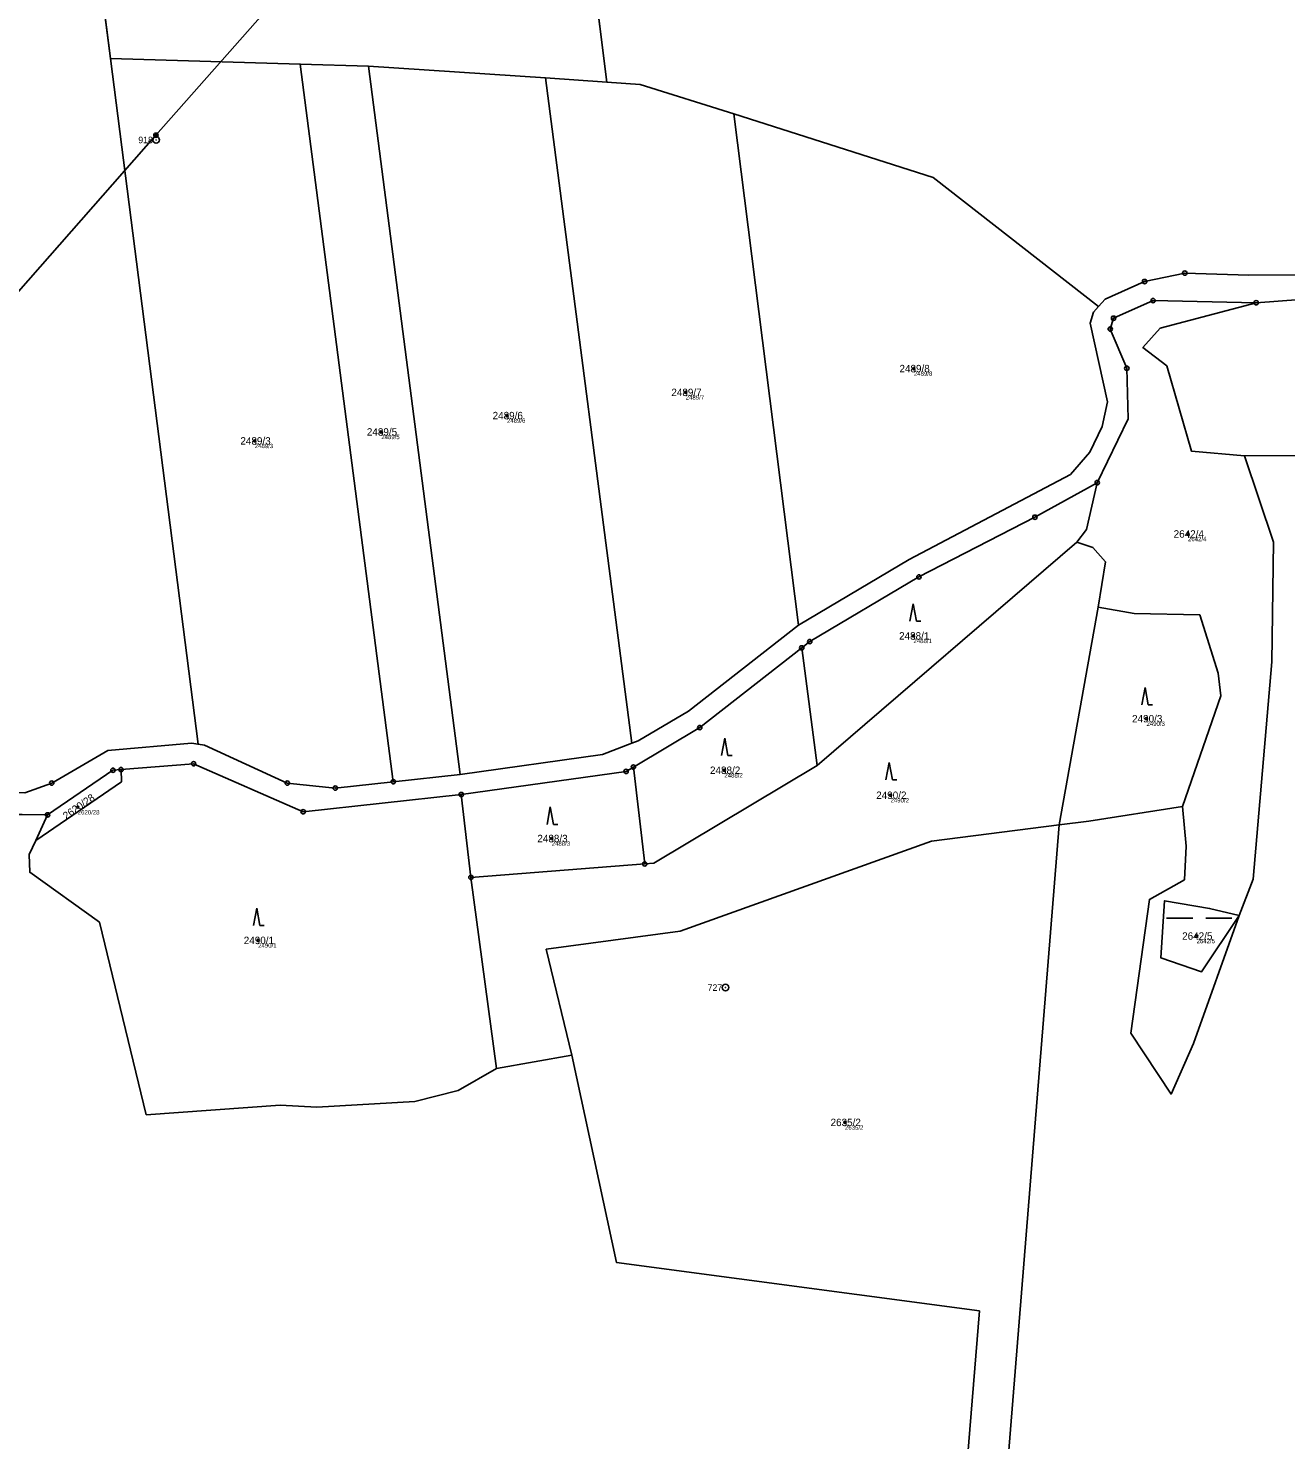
# Model space of a CAD drawing. Extents: x -761891 to -756141, y -1178507 to -1171885.
# Drawn here: x -759249.4 to -758960.9, y -1175617.5 to -1175293.7 of the extents above; entities that cross this region are included whole.
import ezdxf

# ---------------------------------------------------------------- set-up
doc = ezdxf.new("R2010")
doc.units = 0
for name, color, linetype in [('Definiční body', 7, 'Continuous'), ('Hranice parcel', 7, 'Continuous'), ('Parcelní čísla', 7, 'Continuous'), ('Polygon parcely', 7, 'Continuous'), ('Poz předměty', 7, 'Continuous'), ('Značky bodu BP', 7, 'Continuous'), ('Značky kultur', 7, 'Continuous')]:
    doc.layers.add(name, color=color, linetype=linetype)

msp = doc.modelspace()

# ---------------------------------------------------------------- linework, layer by layer
at = {"layer": 'Definiční body'}
for centre in [(-759046.21, -1175371.74), (-759098.55, -1175377.2), (-759139.55, -1175382.52), (-759197.41, -1175388.33), (-759168.39, -1175386.27), (-758983.32, -1175409.67), (-759046.31, -1175433.06), (-758992.85, -1175452.05), (-759089.68, -1175463.88), (-759238.01, -1175472.36), (-759051.56, -1175469.61), (-759129.29, -1175479.54), (-758981.36, -1175501.9), (-759196.63, -1175502.91), (-759062.01, -1175544.66)]:
    msp.add_circle(centre, 0.25, dxfattribs=at)
at = {"layer": 'Hranice parcel'}
for p, q in [((-759230.51, -1175300.62), (-759239.1, -1175233.43)), ((-759124.57, -1175242.76), (-759116.61, -1175306.03)), ((-759210.41, -1175457.91), (-759230.51, -1175300.62)), ((-759186.97, -1175301.88), (-759230.51, -1175300.62)), ((-759165.64, -1175466.52), (-759186.97, -1175301.88)), ((-759186.97, -1175301.88), (-759171.32, -1175302.34)), ((-759171.32, -1175302.34), (-759150.26, -1175464.85)), ((-759171.32, -1175302.34), (-759130.69, -1175305.08)), ((-759130.69, -1175305.08), (-759110.92, -1175457.7)), ((-759130.69, -1175305.08), (-759116.61, -1175306.03)), ((-759087.54, -1175313.33), (-759072.7, -1175430.56)), ((-759008.83, -1175411.55), (-759068.36, -1175462.82)), ((-759003.9, -1175426.45), (-759012.92, -1175476.42)), ((-759071.93, -1175435.8), (-759068.36, -1175462.82)), ((-759150.26, -1175464.85), (-759165.64, -1175466.52)), ((-759110.54, -1175463.15), (-759107.94, -1175485.36)), ((-759147.83, -1175488.47), (-759150.05, -1175469.45)), ((-759274.94, -1175473.79), (-759244.94, -1175474.11)), ((-759247.64, -1175479.98), (-759244.94, -1175474.11)), ((-759107.94, -1175485.36), (-759147.83, -1175488.47)), ((-759141.95, -1175532.33), (-759147.83, -1175488.47)), ((-759124.69, -1175529.2), (-759141.95, -1175532.33))]:
    msp.add_line(p, q, dxfattribs=at)
for points in [[(-758695.3, -1175253.59), (-758701.44, -1175256.15), (-758706.31, -1175261.2), (-758730.9, -1175293.88), (-758746.46, -1175305.02), (-758759.1, -1175309.68), (-758817.04, -1175324.96), (-758849.31, -1175338.47), (-758893.74, -1175347.18), (-758929.46, -1175350.12), (-758969.35, -1175350.34), (-758984.06, -1175349.84), (-758993.3, -1175351.77), (-759002.36, -1175355.79), (-759003.87, -1175357.51)], [(-759116.61, -1175306.03), (-759108.97, -1175306.54), (-759087.54, -1175313.33)], [(-759087.54, -1175313.33), (-759041.78, -1175327.91), (-759003.87, -1175357.51)], [(-758967.69, -1175356.63), (-758957.61, -1175355.92), (-758936.92, -1175355.2), (-758892.8, -1175353.02)], [(-759003.87, -1175357.51), (-759005.01, -1175358.82), (-759005.75, -1175361.32), (-759001.76, -1175379.4), (-759003.02, -1175385), (-759005.87, -1175390.89), (-759010.3, -1175396.05), (-759047.29, -1175415.5), (-759072.7, -1175430.56)], [(-759004.16, -1175397.91), (-758997.06, -1175383.23), (-758997.36, -1175371.67), (-759001.15, -1175362.68), (-759000.41, -1175360.18), (-758991.35, -1175356.15), (-758967.69, -1175356.63)], [(-758967.69, -1175356.63), (-758989.69, -1175362.44), (-758993.67, -1175366.93), (-758988.15, -1175371.11), (-758982.56, -1175390.67), (-758970.34, -1175391.79)], [(-758970.34, -1175391.79), (-758896.65, -1175391.68), (-758878, -1175385.58), (-758877.56, -1175382.43)], [(-758984.56, -1175472.16), (-758983.74, -1175481.33), (-758984.15, -1175488.98), (-758992.19, -1175493.5), (-758996.44, -1175524.19), (-758987.22, -1175538.18), (-758982.03, -1175526.53), (-758971.62, -1175497.23), (-758968.41, -1175488.86), (-758964.07, -1175438.99), (-758963.69, -1175411.57), (-758970.34, -1175391.79)], [(-759071.93, -1175435.8), (-759070.1, -1175434.37), (-759045.06, -1175419.53), (-759018.46, -1175405.83), (-759004.16, -1175397.91)], [(-759004.16, -1175397.91), (-759006.64, -1175408.62), (-759008.83, -1175411.55)], [(-759008.83, -1175411.55), (-759005.17, -1175412.8), (-759002.27, -1175416.06), (-759003.9, -1175426.45)], [(-759003.9, -1175426.45), (-758995.67, -1175427.92), (-758980.65, -1175428.25), (-758976.42, -1175441.59), (-758975.79, -1175446.77), (-758984.56, -1175472.16)], [(-759072.7, -1175430.56), (-759097.94, -1175450.29), (-759109.43, -1175457.14), (-759110.92, -1175457.7)], [(-759110.54, -1175463.15), (-759095.34, -1175454.1), (-759071.93, -1175435.8)], [(-759210.41, -1175457.91), (-759211.95, -1175457.67), (-759231.12, -1175459.35), (-759243.97, -1175466.82), (-759250.12, -1175469.05), (-759272.12, -1175468.82)], [(-759165.64, -1175466.52), (-759178.94, -1175467.96), (-759189.96, -1175466.83), (-759208.95, -1175458.12), (-759210.41, -1175457.91)], [(-759110.92, -1175457.7), (-759117.67, -1175460.27), (-759150.26, -1175464.85)], [(-759228.09, -1175463.72), (-759211.43, -1175462.39), (-759186.31, -1175473.39), (-759150.05, -1175469.45)], [(-759068.36, -1175462.82), (-759105.84, -1175485.19), (-759107.94, -1175485.36)], [(-759228.09, -1175463.72), (-759227.96, -1175466.53), (-759247.64, -1175479.98)], [(-759244.94, -1175474.11), (-759229.95, -1175463.87), (-759228.09, -1175463.72)], [(-759150.05, -1175469.45), (-759112.22, -1175464.15), (-759110.54, -1175463.15)], [(-758984.56, -1175472.16), (-759006.08, -1175475.55), (-759012.92, -1175476.42)], [(-759124.69, -1175529.2), (-759130.53, -1175504.94), (-759099.79, -1175500.8), (-759042.19, -1175480.16), (-759012.92, -1175476.42)], [(-759012.92, -1175476.42), (-759024.01, -1175615.13), (-759035.11, -1175753.97)], [(-759247.64, -1175479.98), (-759249.13, -1175483.21), (-759249.01, -1175487.28), (-759233.01, -1175498.74), (-759222.29, -1175542.91), (-759191.58, -1175540.71), (-759183.19, -1175541.19), (-759160.7, -1175539.89), (-759150.72, -1175537.34), (-759141.95, -1175532.33)], [(-758971.62, -1175497.23), (-758980.2, -1175510.1), (-758989.59, -1175506.87), (-758988.69, -1175493.8), (-758978.38, -1175495.59), (-758971.62, -1175497.23)], [(-759044.36, -1175750.29), (-759031.17, -1175587.92), (-759114.42, -1175576.8), (-759124.69, -1175529.2)]]:
    msp.add_lwpolyline(points, dxfattribs=at)
at = {"layer": 'Polygon parcely'}
for points in [[(-759171.32, -1175302.34), (-759130.69, -1175305.08), (-759116.61, -1175306.03), (-759124.57, -1175242.76), (-759208.65, -1175251.43), (-759212.91, -1175218.59), (-759239.1, -1175233.43), (-759230.51, -1175300.62), (-759186.97, -1175301.88)], [(-759210.41, -1175457.91), (-759230.51, -1175300.62), (-759239.1, -1175233.43), (-759263.85, -1175246.81), (-759298.74, -1175260.61), (-759285.43, -1175364.72), (-759272.12, -1175468.82), (-759250.12, -1175469.05), (-759243.97, -1175466.82), (-759231.12, -1175459.35), (-759211.95, -1175457.67)], [(-759230.51, -1175300.62), (-759210.41, -1175457.91), (-759208.95, -1175458.12), (-759189.96, -1175466.83), (-759178.94, -1175467.96), (-759165.64, -1175466.52), (-759186.97, -1175301.88)], [(-759165.64, -1175466.52), (-759150.26, -1175464.85), (-759171.32, -1175302.34), (-759186.97, -1175301.88)], [(-759150.26, -1175464.85), (-759117.67, -1175460.27), (-759110.92, -1175457.7), (-759130.69, -1175305.08), (-759171.32, -1175302.34)], [(-759130.69, -1175305.08), (-759110.92, -1175457.7), (-759109.43, -1175457.14), (-759097.94, -1175450.29), (-759072.7, -1175430.56), (-759087.54, -1175313.33), (-759108.97, -1175306.54), (-759116.61, -1175306.03)], [(-759072.7, -1175430.56), (-759047.29, -1175415.5), (-759010.3, -1175396.05), (-759005.87, -1175390.89), (-759003.02, -1175385), (-759001.76, -1175379.4), (-759005.75, -1175361.32), (-759005.01, -1175358.82), (-759003.87, -1175357.51), (-759041.78, -1175327.91), (-759087.54, -1175313.33)], [(-758970.34, -1175391.79), (-758896.65, -1175391.68), (-758878, -1175385.58), (-758877.56, -1175382.43), (-758879.52, -1175379.64), (-758881.42, -1175374.43), (-758882.21, -1175367.16), (-758882.49, -1175364.51), (-758882.67, -1175362.89), (-758886.6, -1175357.63), (-758892.8, -1175353.02), (-758936.92, -1175355.2), (-758957.61, -1175355.92), (-758967.69, -1175356.63), (-758989.69, -1175362.44), (-758993.67, -1175366.93), (-758988.15, -1175371.11), (-758982.56, -1175390.67)], [(-758971.62, -1175497.23), (-758968.41, -1175488.86), (-758964.07, -1175438.99), (-758963.69, -1175411.57), (-758970.34, -1175391.79), (-758982.56, -1175390.67), (-758988.15, -1175371.11), (-758993.67, -1175366.93), (-758989.69, -1175362.44), (-758967.69, -1175356.63), (-758991.35, -1175356.15), (-759000.41, -1175360.18), (-759001.15, -1175362.68), (-758997.36, -1175371.67), (-758997.06, -1175383.23), (-759004.16, -1175397.91), (-759006.64, -1175408.62), (-759008.83, -1175411.55), (-759005.17, -1175412.8), (-759002.27, -1175416.06), (-759003.9, -1175426.45), (-758995.67, -1175427.92), (-758980.65, -1175428.25), (-758976.42, -1175441.59), (-758975.79, -1175446.77), (-758984.56, -1175472.16), (-758983.74, -1175481.33), (-758984.15, -1175488.98), (-758992.19, -1175493.5), (-758996.44, -1175524.19), (-758987.22, -1175538.18), (-758982.03, -1175526.53)], [(-759068.36, -1175462.82), (-759008.83, -1175411.55), (-759006.64, -1175408.62), (-759004.16, -1175397.91), (-759018.46, -1175405.83), (-759045.06, -1175419.53), (-759070.1, -1175434.37), (-759071.93, -1175435.8)], [(-759012.92, -1175476.42), (-759003.9, -1175426.45), (-759002.27, -1175416.06), (-759005.17, -1175412.8), (-759008.83, -1175411.55), (-759068.36, -1175462.82), (-759105.84, -1175485.19), (-759107.94, -1175485.36), (-759147.83, -1175488.47), (-759141.95, -1175532.33), (-759124.69, -1175529.2), (-759130.53, -1175504.94), (-759099.79, -1175500.8), (-759042.19, -1175480.16)], [(-759003.9, -1175426.45), (-759012.92, -1175476.42), (-759006.08, -1175475.55), (-758984.56, -1175472.16), (-758975.79, -1175446.77), (-758976.42, -1175441.59), (-758980.65, -1175428.25), (-758995.67, -1175427.92)], [(-759110.54, -1175463.15), (-759107.94, -1175485.36), (-759105.84, -1175485.19), (-759068.36, -1175462.82), (-759071.93, -1175435.8), (-759095.34, -1175454.1)], [(-759228.09, -1175463.72), (-759227.96, -1175466.53), (-759247.64, -1175479.98), (-759249.13, -1175483.21), (-759249.01, -1175487.28), (-759233.01, -1175498.74), (-759222.29, -1175542.91), (-759191.58, -1175540.71), (-759183.19, -1175541.19), (-759160.7, -1175539.89), (-759150.72, -1175537.34), (-759141.95, -1175532.33), (-759147.83, -1175488.47), (-759150.05, -1175469.45), (-759186.31, -1175473.39), (-759211.43, -1175462.39)], [(-759228.09, -1175463.72), (-759229.95, -1175463.87), (-759244.94, -1175474.11), (-759247.64, -1175479.98), (-759227.96, -1175466.53)], [(-759110.54, -1175463.15), (-759112.22, -1175464.15), (-759150.05, -1175469.45), (-759147.83, -1175488.47), (-759107.94, -1175485.36)], [(-759124.69, -1175529.2), (-759114.42, -1175576.8), (-759031.17, -1175587.92), (-759044.36, -1175750.29), (-759041.58, -1175759.49), (-759035.11, -1175753.97), (-759024.01, -1175615.13), (-759012.92, -1175476.42), (-759042.19, -1175480.16), (-759099.79, -1175500.8), (-759130.53, -1175504.94)], [(-758971.62, -1175497.23), (-758980.2, -1175510.1), (-758989.59, -1175506.87), (-758988.69, -1175493.8), (-758978.38, -1175495.59)], [(-758971.62, -1175497.23), (-758978.38, -1175495.59), (-758988.69, -1175493.8), (-758989.59, -1175506.87), (-758980.2, -1175510.1)]]:
    msp.add_lwpolyline(points, close=True, dxfattribs=at)
for points in [[(-759124.57, -1175242.76), (-759116.61, -1175306.03), (-759108.97, -1175306.54), (-759087.54, -1175313.33), (-759041.78, -1175327.91), (-759003.87, -1175357.51), (-759002.36, -1175355.79), (-758993.3, -1175351.77), (-758984.06, -1175349.84), (-758969.35, -1175350.34), (-758929.46, -1175350.12), (-758893.74, -1175347.18), (-758849.31, -1175338.47), (-758817.04, -1175324.96), (-758759.1, -1175309.68), (-758746.46, -1175305.02), (-758730.9, -1175293.88), (-758706.31, -1175261.2)], [(-758929.46, -1175350.12), (-758969.35, -1175350.34), (-758984.06, -1175349.84), (-758993.3, -1175351.77), (-759002.36, -1175355.79), (-759003.87, -1175357.51), (-759005.01, -1175358.82), (-759005.75, -1175361.32), (-759001.76, -1175379.4), (-759003.02, -1175385), (-759005.87, -1175390.89), (-759010.3, -1175396.05), (-759047.29, -1175415.5), (-759072.7, -1175430.56), (-759097.94, -1175450.29), (-759109.43, -1175457.14), (-759110.92, -1175457.7), (-759117.67, -1175460.27), (-759150.26, -1175464.85), (-759165.64, -1175466.52), (-759178.94, -1175467.96), (-759189.96, -1175466.83), (-759208.95, -1175458.12), (-759210.41, -1175457.91), (-759211.95, -1175457.67), (-759231.12, -1175459.35), (-759243.97, -1175466.82), (-759250.12, -1175469.05)], [(-759274.94, -1175473.79), (-759244.94, -1175474.11), (-759229.95, -1175463.87), (-759228.09, -1175463.72), (-759211.43, -1175462.39), (-759186.31, -1175473.39), (-759150.05, -1175469.45), (-759112.22, -1175464.15), (-759110.54, -1175463.15), (-759095.34, -1175454.1), (-759071.93, -1175435.8), (-759070.1, -1175434.37), (-759045.06, -1175419.53), (-759018.46, -1175405.83), (-759004.16, -1175397.91), (-758997.06, -1175383.23), (-758997.36, -1175371.67), (-759001.15, -1175362.68), (-759000.41, -1175360.18), (-758991.35, -1175356.15), (-758967.69, -1175356.63), (-758957.61, -1175355.92)], [(-758896.65, -1175391.68), (-758970.34, -1175391.79), (-758963.69, -1175411.57), (-758964.07, -1175438.99), (-758968.41, -1175488.86), (-758971.62, -1175497.23), (-758982.03, -1175526.53), (-758987.22, -1175538.18), (-758996.44, -1175524.19), (-758992.19, -1175493.5), (-758984.15, -1175488.98), (-758983.74, -1175481.33), (-758984.56, -1175472.16), (-759006.08, -1175475.55), (-759012.92, -1175476.42), (-759024.01, -1175615.13), (-759035.11, -1175753.97)], [(-759044.36, -1175750.29), (-759031.17, -1175587.92), (-759114.42, -1175576.8), (-759124.69, -1175529.2), (-759141.95, -1175532.33), (-759150.72, -1175537.34), (-759160.7, -1175539.89), (-759183.19, -1175541.19), (-759191.58, -1175540.71), (-759222.29, -1175542.91), (-759233.01, -1175498.74), (-759249.01, -1175487.28), (-759249.13, -1175483.21), (-759247.64, -1175479.98), (-759244.94, -1175474.11), (-759274.94, -1175473.79), (-759262.56, -1175567.39), (-759292.73, -1175571.71), (-759323.75, -1175576.16), (-759334.43, -1175577.69), (-759338.5, -1175642.39)]]:
    msp.add_lwpolyline(points, dxfattribs=at)
at = {"layer": 'Poz předměty'}
for p, q in [((-759142.03, -1175229.64), (-759220.08, -1175318.2)), ((-759220.08, -1175318.2), (-759293.3, -1175401.37))]:
    msp.add_line(p, q, dxfattribs=at)
for radius in [0.5, 0.4, 0.3, 0.2, 0.1]:
    msp.add_circle((-759220.08, -1175318.2), radius, dxfattribs=at)
at = {"layer": 'Značky bodu BP'}
for centre, radius in [((-759220.03, -1175319.29), 0.75), ((-759220.03, -1175319.29), 0.03), ((-758984.06, -1175349.84), 0.5), ((-758993.3, -1175351.77), 0.5), ((-758993.3, -1175351.77), 0.0303), ((-758984.06, -1175349.84), 0.0303), ((-758991.35, -1175356.15), 0.5), ((-758991.35, -1175356.15), 0.0303), ((-758967.69, -1175356.63), 0.5), ((-758967.69, -1175356.63), 0.0303), ((-759001.15, -1175362.68), 0.5), ((-759000.41, -1175360.18), 0.5), ((-759000.41, -1175360.18), 0.0303), ((-759001.15, -1175362.68), 0.0303), ((-758997.36, -1175371.67), 0.5), ((-758997.36, -1175371.67), 0.0303), ((-759004.16, -1175397.91), 0.5), ((-759004.16, -1175397.91), 0.0303), ((-759018.46, -1175405.83), 0.5), ((-759018.46, -1175405.83), 0.0303), ((-759045.06, -1175419.53), 0.5), ((-759045.06, -1175419.53), 0.0303), ((-759071.93, -1175435.8), 0.5), ((-759071.93, -1175435.8), 0.0303), ((-759070.1, -1175434.37), 0.5), ((-759070.1, -1175434.37), 0.0303), ((-759095.34, -1175454.1), 0.5), ((-759095.34, -1175454.1), 0.0303), ((-759211.43, -1175462.39), 0.5), ((-759211.43, -1175462.39), 0.0303), ((-759110.54, -1175463.15), 0.5), ((-759229.95, -1175463.87), 0.5), ((-759229.95, -1175463.87), 0.0303), ((-759228.09, -1175463.72), 0.5), ((-759228.09, -1175463.72), 0.0303), ((-759165.64, -1175466.52), 0.5), ((-759112.22, -1175464.15), 0.5), ((-759112.22, -1175464.15), 0.0303), ((-759110.54, -1175463.15), 0.0303), ((-759243.97, -1175466.82), 0.5), ((-759243.97, -1175466.82), 0.0303), ((-759189.96, -1175466.83), 0.5), ((-759189.96, -1175466.83), 0.0303), ((-759178.94, -1175467.96), 0.5), ((-759178.94, -1175467.96), 0.0303), ((-759165.64, -1175466.52), 0.0303), ((-759150.05, -1175469.45), 0.5), ((-759150.05, -1175469.45), 0.0303), ((-759244.94, -1175474.11), 0.5), ((-759244.94, -1175474.11), 0.0303), ((-759186.31, -1175473.39), 0.5), ((-759186.31, -1175473.39), 0.0303), ((-759107.94, -1175485.36), 0.5), ((-759107.94, -1175485.36), 0.0303), ((-759147.83, -1175488.47), 0.5), ((-759147.83, -1175488.47), 0.0303), ((-759089.42, -1175513.73), 0.75), ((-759089.42, -1175513.73), 0.03)]:
    msp.add_circle(centre, radius, dxfattribs=at)
at = {"layer": 'Značky kultur'}
for p, q in [((-759046.39, -1175425.7), (-759047.14, -1175429.7)), ((-759045.64, -1175429.7), (-759046.39, -1175425.7)), ((-759045.64, -1175429.7), (-759044.64, -1175429.7)), ((-758993.19, -1175444.87), (-758993.94, -1175448.87)), ((-758992.44, -1175448.87), (-758993.19, -1175444.87)), ((-758992.44, -1175448.87), (-758991.44, -1175448.87)), ((-759089.61, -1175456.51), (-759090.36, -1175460.51)), ((-759088.86, -1175460.51), (-759089.61, -1175456.51)), ((-759088.86, -1175460.51), (-759087.86, -1175460.51)), ((-759051.87, -1175462.07), (-759052.62, -1175466.07)), ((-759051.12, -1175466.07), (-759051.87, -1175462.07)), ((-759051.12, -1175466.07), (-759050.12, -1175466.07)), ((-759129.61, -1175472.3), (-759130.36, -1175476.3)), ((-759128.86, -1175476.3), (-759129.61, -1175472.3)), ((-759128.86, -1175476.3), (-759127.86, -1175476.3)), ((-759196.97, -1175495.49), (-759197.72, -1175499.49)), ((-759196.22, -1175499.49), (-759196.97, -1175495.49)), ((-758988.24, -1175497.82), (-758982.24, -1175497.82)), ((-758979.24, -1175497.82), (-758973.24, -1175497.82)), ((-759196.22, -1175499.49), (-759195.22, -1175499.49))]:
    msp.add_line(p, q, dxfattribs=at)

# ---------------------------------------------------------------- texts
at = {"layer": 'Definiční body'}
for s, p in [('2489/8', (-759046.21, -1175373.4)), ('2489/7', (-759098.55, -1175378.86)), ('2489/6', (-759139.55, -1175384.18)), ('2489/5', (-759168.39, -1175387.93)), ('2489/3', (-759197.41, -1175389.99)), ('2642/4', (-758983.32, -1175411.33)), ('2488/1', (-759046.31, -1175434.72)), ('2490/3', (-758992.85, -1175453.71)), ('2488/2', (-759089.68, -1175465.54)), ('2490/2', (-759051.56, -1175471.27)), ('2620/28', (-759238.01, -1175474.02)), ('2488/3', (-759129.29, -1175481.2)), ('2490/1', (-759196.63, -1175504.57)), ('2642/5', (-758981.36, -1175503.56)), ('2635/2', (-759062.01, -1175546.32))]:
    msp.add_text(s, height=1, dxfattribs=at).set_placement(p)
at = {"layer": 'Parcelní čísla'}
for s, p in [('2489/8', (-759049.52, -1175372.59)), ('2489/7', (-759101.85, -1175378.05)), ('2489/6', (-759142.85, -1175383.37)), ('2489/3', (-759200.71, -1175389.18)), ('2489/5', (-759171.7, -1175387.12)), ('2642/4', (-758986.62, -1175410.52)), ('2488/1', (-759049.61, -1175433.91)), ('2490/3', (-758996.16, -1175452.9)), ('2488/2', (-759092.98, -1175464.73)), ('2490/2', (-759054.86, -1175470.46)), ('2488/3', (-759132.59, -1175480.39)), ('2642/5', (-758984.67, -1175502.75)), ('2490/1', (-759199.94, -1175503.76)), ('2635/2', (-759065.32, -1175545.51))]:
    msp.add_text(s, height=1.7, dxfattribs=at).set_placement(p)
msp.add_text('2620/28', height=1.7, rotation=35, dxfattribs=at).set_placement((-759240.67, -1175475.26))
at = {"layer": 'Značky bodu BP'}
for s, p in [('918', (-759224.13, -1175320.04)), ('727', (-759093.52, -1175514.48))]:
    msp.add_text(s, height=1.5, dxfattribs=at).set_placement(p)

doc.saveas('drawing.dxf')
